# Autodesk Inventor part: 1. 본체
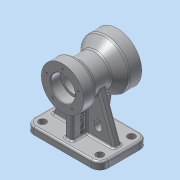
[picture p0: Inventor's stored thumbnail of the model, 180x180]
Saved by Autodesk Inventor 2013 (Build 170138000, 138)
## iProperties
Created: 2015-08
Part Number: 1. 본체
Material: 알루미늄 6061
Document SubType Name: Modeling
Designer: dgall
Density: 2.71 g/cm^3
Mass: 1062.79 g
Surface Area: 749.652 cm^2
Volume: 392.172 cm^3
Author: dgall
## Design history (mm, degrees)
sketch "스케치1"
  geometry: L1 (-61, 40)-(61, 40); L2 (61, 40)-(61, -40); L3 (61, -40)-(-61, -40); L4 (-61, -40)-(-61, 40); 3 further points
  constraints: 8 end point, 2 midpoint, 2 parallel, 1 horizontal, 1 horizontal alignment, 1 perpendicular, 1 vertical alignment
  dimensions: "d0" = 122 distance of L1.start L1.end; "d2" = 80 distance of L1.end L2.end
extrude "돌출1" new body sketch "스케치1" distance "d3" = 12; taper "d4" = 0 deg
fillet "모깎기1" dims "d5" = 14
hole "구멍1" diameter "d8" = 12; stored, may be unused: countersink angle "d12" = 90 deg, drill point angle "d14" = 118 deg; dims "d6" = 10, "d7" = 10, "d9" = 6, "d10" = 4, "d11" = 2, "d13" = 8
hole "구멍2" diameter "d17" = 12; stored, may be unused: countersink angle "d21" = 90 deg, drill point angle "d23" = 118 deg; dims "d15" = 10, "d16" = 10, "d18" = 6, "d19" = 4, "d20" = 2, "d22" = 8
hole "구멍3" diameter "d26" = 12; stored, may be unused: countersink angle "d30" = 90 deg, drill point angle "d32" = 118 deg; dims "d24" = 10, "d25" = 10, "d27" = 6, "d28" = 4, "d29" = 2, "d31" = 8
hole "구멍4" diameter "d35" = 12; stored, may be unused: countersink angle "d39" = 90 deg, drill point angle "d41" = 118 deg; dims "d33" = 10, "d34" = 10, "d36" = 6, "d37" = 4, "d38" = 2, "d40" = 8
sketch "스케치3"
  geometry: L1 (94, 0)-(0, 0) reference; C1 r 26 at (47, 90); 2 further points
  constraints: 1 centre point, 1 midpoint, 1 vertical alignment
  dimensions: "d46" = 26 radius of C1; "d47" = 90 distance of point (47, 0) C1.centre
extrude "돌출2" join sketch "스케치3" distance "d48" = 90; taper "d49" = 0 deg
sketch "스케치5"
  geometry: C1 r 26 at (0, 0) reference; C2 r 35 at (0, 0); 1 further point
  constraints: 1 centre point, 1 coincident
  dimensions: "d57" = 35 radius of C2
extrude "돌출3" join sketch "스케치5" distance "d58" = 20; taper "d59" = 0 deg
sketch "스케치6"
  geometry: C1 r 26 at (0, 0) reference; C2 r 40 at (0, 0); 1 further point
  constraints: 1 centre point, 1 coincident
  dimensions: "d60" = 40 radius of C2
extrude "돌출4" join sketch "스케치6" distance "d61" = 20; taper "d62" = 0 deg
sketch "스케치7"
  geometry: L1 (-40, 55)-(-40, 125) reference; L2 (50, 130)-(50, 50) reference; L3 (-20, 55)-(-20, 125) reference; L4 (-20, 116)-(30, 116) reference; L5 (30, 130)-(30, 50) reference; L6 (-40, 90)-(50, 90); L7 (30, 130)-(13.315, 116); L8 (-20, 125)-(-14.804, 116); 1 further point
  constraints: 6 end point, 2 midpoint, 2 point on line
  dimensions: "d64" = 40 deg angle of L4 L7; "d65" = 60 deg angle of L4 L8
revolve "회전1" sketch "스케치7" stored, may be unused: angle "d66" = 90 deg
sketch "스케치8"
  geometry: C1 r 40 at (0, 0) reference; C2 r 16 at (0, 0); C3 r 20 at (0, 0); 1 further point
  constraints: 2 centre point, 2 coincident
  dimensions: "d67" = 16 radius of C2; "d68" = 20 radius of C3
extrude "돌출5" cut sketch "스케치8" distance "d69" = 100; taper "d70" = 0 deg
sketch "스케치10"
  geometry: L1 (47, 12)-(-47, 12) reference; L2 (-53, 12)-(-41, 12) reference; L3 (41, 12)-(53, 12) reference; L4 (47, 12)-(61, 12) reference; L5 (-61, 12)-(-47, 12) reference; L6 (-29.478, 71.131)-(-51, 12); L7 (29.478, 71.131)-(51, 12); L8 (-61, 0)-(-61, 12) reference; L9 (61, 12)-(61, 0) reference; L10 (-29.478, 71.131)-(-25.091, 83.185); L11 (29.478, 71.131)-(25.091, 83.185); A1 r 35 centre (0, 90) between (-29.478, 71.131) and (29.478, 71.131) reference; A2 r 26 centre (0, 90) between (-25.091, 83.185) and (25.091, 83.185) reference; 1 further point
  constraints: 8 end point, 4 point on circle, 2 collinear, 2 point on line, 1 horizontal alignment
  dimensions: "d79" = 10 distance from line of L6.end L8; "d80" = 10 distance from line of L7.end L9; "d81" = 70 deg angle of L6 L1; "d82" = 70 deg angle of L1 L7 (derived)
extrude "돌출9" join sketch "스케치10" stored distance "d83" = 12; taper "d84" = 0 deg
sketch "스케치11"
  geometry: L1 (-51, -12)-(51, -12) reference; L2 (30, -36)-(30, -30); L3 (18, -30)-(18, -36); A1 r 6 centre (24, -30) between (30, -30) and (18, -30); A2 r 6 centre (24, -36) between (18, -36) and (30, -36); 1 further point
  constraints: 4 end point, 4 point on circle, 4 tangent, 2 centre point, 1 parallel, 1 perpendicular
  dimensions: "d85" = 24 horizontal distance of point (0, 0) A1.centre; "d86" = 18 dimension on A1 A2; "d87" = 12 distance between parallel lines of L3 L2; "d88" = 18 distance from line of A1.centre L1
extrude "돌출10" cut sketch "스케치11" distance "d89" = 12; taper "d90" = 0 deg
sketch "스케치12"
  geometry: L1 (-40, 55)-(-20, 55) reference; L2 (-40, 12)-(-26, 12) reference; L3 (-32, 12)-(-20, 12) reference; L4 (26, 12)-(-26, 12) reference; L5 (-20, 55)-(-14.804, 64) reference; L6 (-14.804, 64)-(13.315, 64) reference; L7 (13.315, 64)-(30, 50) reference; L8 (30, 130)-(30, 50) reference; L9 (50, 130)-(50, 50) reference; L10 (50, 50)-(30, 50) reference; L11 (20, 12)-(32, 12) reference; L12 (26, 12)-(40, 12) reference; L13 (-30, 55)-(-30, 12); L14 (30, 12)-(36.7, 50); L15 (-40, 0)-(-40, 12) reference; L16 (40, 12)-(40, 0) reference; L17 (-30, 55)-(-30, 60.483); L18 (-30, 60.483)-(-19.914, 60.483); L19 (-19.914, 60.483)-(-14, 67.531); L20 (-14, 67.531)-(16.299, 67.531); L21 (16.299, 67.531)-(32.404, 58.233); L22 (36.7, 50)-(37.979, 57.25); L23 (37.979, 57.25)-(32.404, 58.233); L24 (-30, 12)-(30, 12); 1 further point
  constraints: 20 end point, 5 perpendicular, 3 point on line, 2 collinear, 2 parallel, 1 midpoint
  dimensions: "d91" = 10 distance between parallel lines of L13 L15; "d92" = 10 distance from line of L14.start L16; "d93" = 80 deg angle of L12 L14
extrude "돌출11" join sketch "스케치12" stored distance "d94" = 12; taper "d95" = 0 deg
sketch "스케치13"
  geometry: L1 (-55.518, -30)-(-12, -30) reference; L2 (-12, -6)-(-12, -30) reference; 2 further points
  constraints: 1 other
  dimensions: "d96" = 16 distance from line of L1 point (-36, -14); "d97" = 24 distance from line of point (-36, -14) L2
extrude "돌출12" join sketch "스케치13" distance "d98" = 0.5; taper "d99" = 0 deg
sketch "스케치15"
  geometry: C1 r 16 at (0, 0) reference; C2 r 40 at (0, 0) reference; C3 r 26 at (0, 0); C4 r 19 at (0, 0); 1 further point
  constraints: 2 centre point, 2 coincident
  dimensions: "d112" = 26 radius of C3; "d113" = 19 radius of C4
extrude "돌출13" cut sketch "스케치15" distance "d114" = 23; taper "d115" = 0 deg
extrude "돌출14" cut sketch "스케치15" distance "d116" = 20; taper "d117" = 0 deg
sketch "스케치16"
  geometry: C1 r 16 at (0, 0) reference; C2 r 35 at (0, 0) reference; C3 r 20 at (0, 0); 1 further point
  constraints: 1 centre point, 1 coincident
  dimensions: "d118" = 20 radius of C3
extrude "돌출15" cut sketch "스케치16" distance "d119" = 17; taper "d120" = 0 deg
sketch "스케치17" dims "d121" = 33
  geometry: C1 r 40 at (0, 0) reference; 3 further points
  constraints: 2 vertical alignment, 1 coincident, 2 other
hole "구멍6" sketch "스케치17" at (0, -33) diameter "d122" = 3.242; stored, may be unused: countersink angle "d126" = 90 deg, drill point angle "d128" = 118 deg; dims "d123" = 10, "d124" = 4, "d125" = 2, "d127" = 13
sketch "스케치18" dims "d132" = 27
  geometry: C1 r 35 at (0, 0) reference; 3 further points
  constraints: 2 vertical alignment, 1 coincident, 2 other
hole "구멍7" sketch "스케치18" at (0, 27) diameter "d133" = 3.242; stored, may be unused: countersink angle "d137" = 90 deg, drill point angle "d139" = 118 deg; dims "d134" = 10, "d135" = 4, "d136" = 2, "d138" = 13
fillet "모깎기2" dims "d143" = 5
fillet "모깎기3" dims "d144" = 5
fillet "모깎기4" dims "d145" = 0.3
fillet "모깎기5" dims "d146" = 3
fillet "모깎기6" dims "d147" = 3
fillet "모깎기7" dims "d148" = 3
fillet "모깎기8" dims "d149" = 3
fillet "모깎기9" dims "d150" = 3
fillet "모깎기10" dims "d151" = 3
chamfer "모따기1" distance "d152" = 1; stored, may be unused: second distance "d153" = 2, angle "d154" = 45 deg
node "솔리드1"
mirror "대칭1"
pattern_circular "원형 패턴2" dims angle "d130" = 360 deg
pattern_circular "원형 패턴3" dims angle "d141" = 360 deg
node "투영된 루프5"
